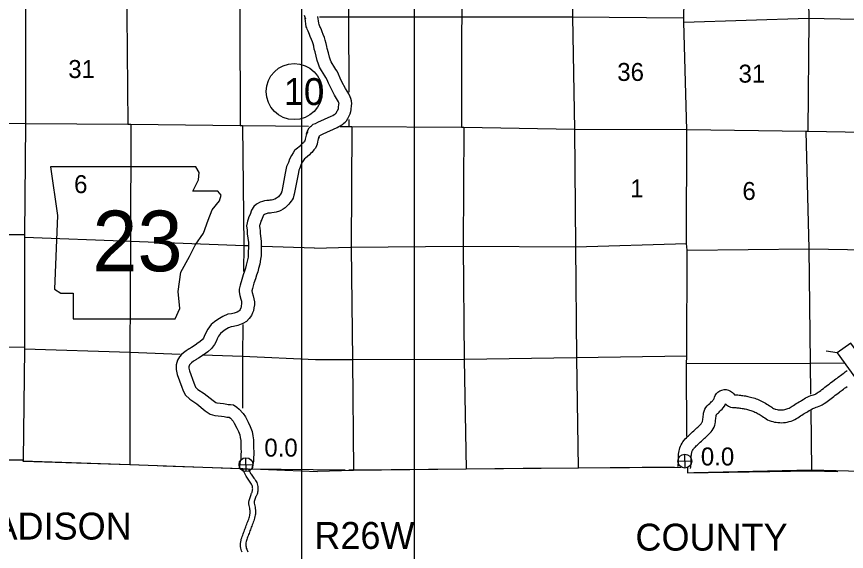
# Model space of a CAD drawing. Extents: x 77230 to 630905, y 790554 to 1662844.
# Drawn here: x 354221 to 393234, y 1564948 to 1590114 of the extents above; entities that cross this region are included whole.
import ezdxf

# ---------------------------------------------------------------- set-up
doc = ezdxf.new("R2010")
doc.units = 0
for name, color, linetype in [('Level 10', 7, 'Continuous'), ('Level 15', 7, 'Continuous'), ('Level 16', 7, 'Continuous'), ('Level 18', 7, 'Continuous'), ('Level 19', 7, 'Continuous'), ('Level 22', 7, 'Continuous'), ('Level 24', 7, 'Continuous'), ('Level 28', 7, 'Continuous'), ('Level 31', 7, 'Continuous'), ('Level 33', 7, 'Continuous'), ('Level 34', 7, 'Continuous'), ('Level 43', 7, 'Continuous')]:
    doc.layers.add(name, color=color, linetype=linetype)

msp = doc.modelspace()

# ---------------------------------------------------------------- linework, layer by layer
at = {"layer": 'Level 10'}
for points in [[(364825, 1564913), (364802, 1564974), (364781, 1565039), (364765, 1565107), (364754, 1565177), (364749, 1565248), (364750, 1565320), (364758, 1565392), (364773, 1565471), (364787, 1565528), (364807, 1565593), (364828, 1565654), (364850, 1565712), (364871, 1565770), (364893, 1565827), (364914, 1565883), (364935, 1565940), (364956, 1565997), (364978, 1566054), (365000, 1566112), (365022, 1566171), (365044, 1566231), (365067, 1566290), (365090, 1566349), (365111, 1566407), (365133, 1566465), (365152, 1566523), (365169, 1566580), (365183, 1566637), (365194, 1566696), (365198, 1566728), (365203, 1566813), (365201, 1566869), (365194, 1566927), (365184, 1566986), (365171, 1567048), (365157, 1567116), (365146, 1567189), (365143, 1567265), (365149, 1567349), (365243, 1567628), (365257, 1567657), (365269, 1567683), (365281, 1567710), (365292, 1567737), (365303, 1567766), (365311, 1567794), (365316, 1567823), (365319, 1567855), (365320, 1567891), (365318, 1567929), (365314, 1567968), (365306, 1568005), (365295, 1568043), (365280, 1568079), (365261, 1568117), (365236, 1568157), (365207, 1568201), (365175, 1568247), (365143, 1568294), (365111, 1568341), (365078, 1568388), (365043, 1568438), (365010, 1568490), (364977, 1568547), (364947, 1568609), (364915, 1568672), (364880, 1568778), (364875, 1568839), (365126, 1568836)], [(365126, 1568836), (365137, 1568789), (365157, 1568743), (365181, 1568699), (365198, 1568664), (365224, 1568621), (365252, 1568575), (365283, 1568530), (365316, 1568483), (365348, 1568436), (365381, 1568389), (365414, 1568342), (365447, 1568292), (365479, 1568240), (365508, 1568183), (365532, 1568125), (365549, 1568065), (365561, 1568006), (365567, 1567949), (365570, 1567895), (365569, 1567840), (365564, 1567787), (365554, 1567736), (365541, 1567690), (365526, 1567649), (365511, 1567611), (365496, 1567578), (365484, 1567552), (365476, 1567535), (365396, 1567299), (365393, 1567262), (365395, 1567213), (365403, 1567159), (365416, 1567100), (365430, 1567034), (365442, 1566963), (365451, 1566889), (365454, 1566810), (365447, 1566705), (365441, 1566658), (365428, 1566585), (365411, 1566514), (365390, 1566447), (365368, 1566382), (365346, 1566321), (365323, 1566261), (365301, 1566201), (365278, 1566142), (365256, 1566083), (365234, 1566024), (365212, 1565967), (365191, 1565909), (365169, 1565852), (365148, 1565796), (365127, 1565739), (365106, 1565682), (365084, 1565626), (365064, 1565570), (365045, 1565514), (365028, 1565460), (365017, 1565417), (365005, 1565355), (365000, 1565305), (364999, 1565255), (365003, 1565205), (365010, 1565156), (365022, 1565107), (365038, 1565057), (365058, 1565005), (365090, 1564929)]]:
    msp.add_lwpolyline(points, dxfattribs=at)
at = {"layer": 'Level 15'}
for points in [[(385737, 1570366), (385723, 1573779), (385728, 1574142), (385742, 1579119), (385724, 1579431), (385733, 1584779), (385590, 1589858), (385587, 1590060), (385688, 1594740)], [(354624, 1594312), (354645, 1590288), (354644, 1585065), (354598, 1579843), (354599, 1579713), (354592, 1574536), (354586, 1574466), (354526, 1569264)], [(367944, 1584949), (364841, 1584980), (364732, 1584975), (359592, 1585040), (359446, 1585039), (354660, 1585067), (351771, 1585111)], [(402337, 1584581), (402130, 1584589), (401996, 1584588), (396829, 1584617), (396669, 1584618), (391418, 1584708), (391330, 1584704), (385741, 1584779), (380454, 1584798), (375249, 1584892), (375133, 1584892), (369975, 1584925), (369847, 1584924), (369429, 1584930)]]:
    msp.add_lwpolyline(points, dxfattribs=at)
at = {"layer": 'Level 16'}
for points in [[(364659, 1594455), (364714, 1590160), (364732, 1584975)], [(375149, 1594584), (375133, 1584892)], [(380314, 1594659), (380350, 1590095), (380458, 1584808), (380504, 1579303), (380538, 1574064), (380630, 1568872)], [(391369, 1594782), (391463, 1590012), (391418, 1584708)], [(359314, 1594367), (359397, 1590218), (359446, 1585039)], [(369798, 1592776), (369827, 1590083), (369840, 1586563)], [(368466, 1590107), (369837, 1590098), (375062, 1590096), (380320, 1590095), (385587, 1590060)], [(385590, 1589858), (391447, 1590032), (396639, 1589923), (401897, 1589918), (404848, 1589866)], [(369845, 1585279), (369847, 1584924)], [(359592, 1585040), (359579, 1579528), (359549, 1574321), (359550, 1569034)], [(364841, 1584980), (364908, 1579342), (364892, 1578126)], [(369975, 1584925), (369944, 1579250), (370018, 1573958), (370064, 1568761)], [(375249, 1584892), (375224, 1579318), (375271, 1573971), (375353, 1568811)], [(391330, 1584704), (391468, 1579209), (391536, 1573830), (391550, 1572343)], [(354598, 1579843), (349364, 1579840), (344063, 1579928), (340508, 1579977)], [(365085, 1579324), (364917, 1579330), (359585, 1579536), (354599, 1579713)], [(368230, 1579211), (365767, 1579300)], [(368230, 1579211), (369924, 1579258), (375223, 1579304), (380495, 1579275), (385724, 1579431)], [(385742, 1579119), (391476, 1579183), (396904, 1579089), (402262, 1578987), (402496, 1578985)], [(364857, 1575618), (364837, 1574123), (364843, 1571686)], [(354592, 1574536), (349283, 1574582), (345273, 1574646)], [(361915, 1574217), (359559, 1574301), (354586, 1574466)], [(368273, 1573968), (364849, 1574113), (362958, 1574180)], [(385728, 1574142), (380534, 1574062), (375279, 1573979), (370020, 1573960), (368273, 1573968)], [(393140, 1573813), (391518, 1573792), (385723, 1573779)], [(391557, 1571630), (391586, 1568764)]]:
    msp.add_lwpolyline(points, dxfattribs=at)
at = {"layer": 'Level 18'}
for points in [[(346093, 1569364), (349212, 1569300), (354526, 1569264), (354523, 1569202), (359550, 1569034), (364699, 1568853)], [(365299, 1568830), (368370, 1568710)], [(385134, 1568915), (380630, 1568872), (378034, 1568843), (375353, 1568811), (370064, 1568761), (368370, 1568710)], [(395649, 1568655), (391586, 1568764), (386057, 1568649)]]:
    msp.add_lwpolyline(points, dxfattribs=at)
at = {"layer": 'Level 19'}
msp.add_line((392797, 1574288), (392275, 1574372), dxfattribs=at)
msp.add_lwpolyline([(392797, 1574288), (394188, 1572361), (394830, 1572825), (393439, 1574751)], close=True, dxfattribs=at)
at = {"layer": 'Level 22'}
for p, q in [((388543, 1572250), (388548, 1572249)), ((388429, 1571661), (388425, 1571662))]:
    msp.add_line(p, q, dxfattribs=at)
for points in [[(367738, 1590180), (367771, 1590088), (367799, 1590001)], [(367856, 1584601), (367906, 1584762), (367981, 1584881), (368041, 1584943), (368086, 1584979), (368167, 1585051), (368276, 1585086), (368382, 1585139), (369017, 1585426), (369083, 1585466), (369159, 1585502), (369174, 1585510), (369181, 1585516), (369210, 1585540), (369235, 1585565), (369244, 1585574), (369257, 1585598), (369299, 1585683), (369320, 1585713), (369325, 1585724), (369335, 1585746), (369349, 1585794), (369354, 1585814), (369360, 1585885), (369372, 1585953), (369377, 1585998), (369380, 1586020), (369378, 1586046), (369369, 1586075), (369361, 1586096), (369314, 1586185), (369168, 1586424), (368972, 1586786), (368886, 1586984), (368817, 1587145), (368761, 1587250), (368717, 1587327), (368641, 1587452), (368554, 1587571), (368463, 1587728), (368408, 1587874), (368356, 1588046), (368308, 1588257), (368251, 1588449), (368216, 1588587), (368195, 1588722), (368164, 1588829), (368132, 1588920), (368081, 1589039), (368029, 1589175), (367993, 1589267), (367956, 1589354), (367924, 1589425), (367888, 1589524), (367867, 1589579), (367839, 1589637), (367791, 1590043)], [(368429, 1584423), (368455, 1584506), (368470, 1584519), (368504, 1584530), (368640, 1584597), (369299, 1584895), (369368, 1584937), (369434, 1584968), (369514, 1585013), (369563, 1585053), (369613, 1585094), (369662, 1585143), (369728, 1585212), (369788, 1585317), (369820, 1585381), (369846, 1585420), (369872, 1585478), (369896, 1585532), (369931, 1585642), (369948, 1585726), (369955, 1585808), (369965, 1585864), (369974, 1585931), (369982, 1586010), (369972, 1586152), (369938, 1586267), (369909, 1586345), (369836, 1586482), (369689, 1586723), (369512, 1587050), (369436, 1587223), (369358, 1587404), (369286, 1587540), (369235, 1587630), (369141, 1587786), (369056, 1587901), (369007, 1587985), (368977, 1588066), (368936, 1588201), (368889, 1588409), (368830, 1588607), (368805, 1588708), (368781, 1588853), (368735, 1589012), (368691, 1589137), (368637, 1589264), (368589, 1589391), (368549, 1589493), (368506, 1589593), (368480, 1589653), (368449, 1589734), (368423, 1589804), (368387, 1590112)], [(367907, 1584710), (367868, 1584634), (367828, 1584528), (367805, 1584411), (367787, 1584340), (367775, 1584270), (367774, 1584269), (367769, 1584259), (367745, 1584231), (367704, 1584181), (367677, 1584150), (367623, 1584104), (367562, 1584040), (367501, 1583983), (367433, 1583925), (367367, 1583880), (367293, 1583810), (367227, 1583705), (367147, 1583584), (367055, 1583411), (366998, 1583253), (366968, 1583184), (366918, 1583066), (366885, 1582904), (366850, 1582741), (366690, 1581885), (366683, 1581860), (366675, 1581829), (366629, 1581760), (366593, 1581709), (366568, 1581678), (366531, 1581638), (366483, 1581596), (366441, 1581567), (366355, 1581522), (366350, 1581520), (366272, 1581498), (366207, 1581482), (366132, 1581470), (366084, 1581464), (366028, 1581457), (365983, 1581454), (365876, 1581441), (365778, 1581410), (365668, 1581376), (365507, 1581285), (365377, 1581174), (365267, 1581005), (365196, 1580807), (365141, 1580695), (365112, 1580586), (365082, 1580493), (365058, 1580410), (365035, 1580269), (365057, 1580069), (365067, 1580010), (365064, 1579898), (365118, 1579485), (365121, 1579254), (365115, 1579038), (365115, 1578897), (365101, 1578793), (365066, 1578600), (365019, 1578418), (364980, 1578276), (364935, 1578131), (364880, 1577958), (364804, 1577745), (364736, 1577478), (364684, 1577293), (364685, 1577167), (364715, 1576992), (364762, 1576822), (364791, 1576716), (364800, 1576641), (364801, 1576603), (364781, 1576501), (364772, 1576434), (364758, 1576403), (364727, 1576327), (364701, 1576288), (364662, 1576251), (364587, 1576206), (364454, 1576152), (364318, 1576126), (364151, 1576105), (363921, 1576008), (363677, 1575868), (363529, 1575745), (363371, 1575622), (363213, 1575400), (363105, 1575207), (363047, 1575059), (363015, 1574988), (362955, 1574912), (362838, 1574812), (362760, 1574755), (362609, 1574659), (362440, 1574545), (362347, 1574486)], [(368442, 1584439), (368417, 1584390), (368407, 1584363), (368391, 1584280), (368374, 1584213), (368356, 1584111), (368325, 1584028), (368271, 1583921), (368203, 1583843), (368162, 1583793), (368101, 1583723), (368036, 1583668), (367985, 1583614), (367900, 1583535), (367797, 1583447), (367757, 1583419), (367732, 1583380), (367663, 1583276), (367605, 1583167), (367556, 1583031), (367519, 1582947), (367494, 1582888), (367473, 1582781), (367438, 1582622), (367276, 1581752), (367263, 1581705), (367228, 1581574), (367176, 1581498), (367124, 1581421), (367073, 1581348), (367022, 1581286), (366948, 1581205), (366850, 1581121), (366752, 1581053), (366643, 1580996), (366584, 1580962), (366426, 1580918), (366327, 1580893), (366215, 1580875), (366159, 1580868), (366082, 1580859), (366035, 1580856), (366003, 1580852), (365957, 1580838), (365907, 1580822), (365853, 1580792), (365832, 1580774), (365808, 1580736), (365749, 1580573), (365706, 1580484), (365688, 1580416), (365655, 1580316), (365644, 1580278), (365640, 1580255), (365652, 1580150), (365668, 1580049), (365665, 1579929), (365717, 1579528), (365722, 1579250), (365715, 1579028), (365714, 1578857), (365694, 1578700), (365652, 1578471), (365598, 1578263), (365556, 1578108), (365507, 1577952), (365449, 1577767), (365379, 1577570), (365315, 1577323), (365286, 1577216), (365302, 1577123), (365341, 1576981), (365382, 1576830), (365399, 1576685), (365403, 1576554), (365373, 1576403), (365356, 1576270), (365310, 1576168), (365259, 1576042), (365163, 1575901), (365030, 1575772), (364855, 1575667), (364625, 1575574), (364412, 1575533), (364307, 1575520), (364187, 1575469), (364020, 1575374), (363905, 1575278), (363809, 1575203), (363721, 1575078), (363648, 1574949), (363600, 1574827), (363533, 1574677), (363391, 1574495), (363210, 1574340), (363097, 1574259), (362938, 1574157), (362768, 1574043), (362669, 1573980)], [(362342, 1574483), (362198, 1574388), (362072, 1574294), (361977, 1574210), (361876, 1574107), (361791, 1573948), (361730, 1573735), (361720, 1573512), (361772, 1573273), (361984, 1572678), (362031, 1572553), (362148, 1572320), (362370, 1572104), (362688, 1571896), (363091, 1571568), (363314, 1571402), (363537, 1571339), (363862, 1571319), (363985, 1571292), (364105, 1571270), (364208, 1571266), (364217, 1571260), (364272, 1571212), (364398, 1571078), (364454, 1570984), (364574, 1570753), (364661, 1570583), (364720, 1570427), (364740, 1570308), (364758, 1570160), (364759, 1570013), (364756, 1569811), (364774, 1569611), (364769, 1569538), (364762, 1569380), (364761, 1569280), (364753, 1569239), (364724, 1569119), (364702, 1568977), (364700, 1568891), (364699, 1568856)], [(362674, 1573983), (362543, 1573896), (362451, 1573828), (362391, 1573775), (362365, 1573748), (362351, 1573722), (362326, 1573637), (362323, 1573563), (362350, 1573438), (362547, 1572885), (362581, 1572795), (362639, 1572680), (362748, 1572574), (363042, 1572381), (363460, 1572042), (363584, 1571950), (363638, 1571934), (363946, 1571915), (364104, 1571880), (364172, 1571868), (364284, 1571863), (364417, 1571844), (364577, 1571741), (364688, 1571646), (364880, 1571441), (364979, 1571276), (365107, 1571028), (365210, 1570827), (365303, 1570583), (365333, 1570393), (365358, 1570200), (365359, 1570011), (365357, 1569832), (365375, 1569619), (365369, 1569507), (365362, 1569364), (365361, 1569216), (365338, 1569108), (365313, 1569003), (365301, 1568924), (365300, 1568878), (365299, 1568837)], [(391311, 1572168), (391382, 1572210), (391481, 1572249), (391554, 1572277), (391626, 1572300), (391687, 1572319), (391737, 1572336), (391779, 1572354), (391796, 1572363), (391859, 1572402), (391907, 1572437), (391964, 1572480), (392025, 1572525), (392086, 1572572), (392150, 1572620), (392216, 1572670), (392283, 1572720), (392351, 1572771), (392419, 1572823), (392487, 1572875), (392553, 1572924), (392582, 1572946), (392676, 1573017), (392743, 1573068), (392792, 1573104), (392847, 1573146), (392903, 1573187), (392960, 1573231), (393019, 1573275), (393075, 1573317), (393128, 1573357), (393179, 1573396), (393228, 1573432), (393272, 1573465)], [(391631, 1571660), (391648, 1571670), (391699, 1571690), (391752, 1571710), (391807, 1571728), (391874, 1571749), (391952, 1571776), (392034, 1571811), (392093, 1571841), (392194, 1571904), (392263, 1571954), (392324, 1572000), (392385, 1572046), (392449, 1572093), (392512, 1572142), (392577, 1572191), (392644, 1572241), (392713, 1572293), (392782, 1572345), (392849, 1572396), (392914, 1572445), (392944, 1572468), (393037, 1572538), (393103, 1572588), (393151, 1572624), (393208, 1572666), (393265, 1572709)], [(385312, 1568950), (385317, 1568980), (385323, 1569012), (385328, 1569042), (385332, 1569074), (385336, 1569105), (385338, 1569136), (385340, 1569173), (385341, 1569214), (385342, 1569255), (385342, 1569313), (385342, 1569352), (385343, 1569404), (385343, 1569463), (385347, 1569528), (385353, 1569599), (385365, 1569674), (385383, 1569749), (385406, 1569823), (385433, 1569896), (385467, 1569969), (385506, 1570041), (385551, 1570111), (385602, 1570179), (385656, 1570242), (385711, 1570298), (385763, 1570348), (385812, 1570393), (385861, 1570438), (385909, 1570483), (385957, 1570527), (386006, 1570573), (386055, 1570619), (386105, 1570665), (386154, 1570710), (386203, 1570755), (386252, 1570800), (386299, 1570844), (386342, 1570884), (386377, 1570918), (386404, 1570948), (386425, 1570977), (386444, 1571007), (386459, 1571037), (386470, 1571066), (386473, 1571079), (386484, 1571138), (386490, 1571187), (386496, 1571242), (386501, 1571304), (386511, 1571379), (386523, 1571456), (386546, 1571544), (386582, 1571636), (386630, 1571721), (386688, 1571797), (386746, 1571859), (386806, 1571914), (386840, 1571945), (386881, 1571984), (386921, 1572022), (386955, 1572054), (386974, 1572075), (386984, 1572090), (386995, 1572111), (387010, 1572150), (387034, 1572211), (387070, 1572289), (387125, 1572371), (387196, 1572444), (387283, 1572503), (387378, 1572543), (387481, 1572563), (387585, 1572562), (387691, 1572540), (387791, 1572495), (387878, 1572432), (387939, 1572366), (387974, 1572320), (387977, 1572317), (387979, 1572316), (388023, 1572315), (388076, 1572312), (388134, 1572308), (388192, 1572303), (388250, 1572296), (388307, 1572289), (388367, 1572281), (388426, 1572271), (388485, 1572261), (388543, 1572250)], [(388548, 1572249), (388606, 1572237), (388666, 1572223), (388729, 1572208), (388794, 1572191), (388859, 1572172), (388923, 1572152), (388988, 1572129), (389054, 1572105), (389120, 1572078), (389185, 1572049), (389249, 1572019), (389312, 1571987), (389374, 1571953), (389436, 1571918), (389498, 1571881), (389559, 1571842), (389619, 1571802), (389674, 1571764), (389723, 1571731), (389767, 1571703), (389807, 1571680), (389846, 1571661), (389884, 1571647), (389923, 1571635), (389971, 1571625), (390023, 1571616), (390074, 1571610), (390124, 1571606), (390176, 1571606), (390229, 1571608), (390282, 1571614), (390335, 1571623), (390388, 1571635), (390439, 1571650), (390488, 1571669), (390537, 1571691), (390585, 1571717), (390634, 1571746), (390687, 1571781), (390745, 1571820), (390806, 1571861), (390873, 1571905), (390941, 1571947), (391008, 1571987), (391068, 1572021), (391119, 1572053), (391196, 1572094), (391245, 1572123), (391311, 1572168)], [(385904, 1568850), (385909, 1568879), (385915, 1568914), (385921, 1568954), (385927, 1568998), (385933, 1569047), (385937, 1569100), (385939, 1569150), (385941, 1569200), (385942, 1569251), (385942, 1569309), (385942, 1569349), (385943, 1569399), (385943, 1569443), (385945, 1569485), (385949, 1569523), (385954, 1569558), (385963, 1569593), (385973, 1569628), (385987, 1569665), (386004, 1569701), (386023, 1569736), (386044, 1569769), (386069, 1569802), (386097, 1569835), (386133, 1569871), (386174, 1569910), (386220, 1569953), (386268, 1569997), (386317, 1570042), (386366, 1570088), (386415, 1570134), (386464, 1570179), (386512, 1570224), (386561, 1570269), (386609, 1570314), (386657, 1570358), (386707, 1570403), (386758, 1570451), (386812, 1570505), (386869, 1570569), (386923, 1570640), (386969, 1570716), (387010, 1570797), (387042, 1570882), (387059, 1570947), (387077, 1571047), (387086, 1571118), (387093, 1571186), (387098, 1571240), (387105, 1571291), (387111, 1571334), (387118, 1571360), (387125, 1571376), (387133, 1571391), (387146, 1571408), (387168, 1571432), (387213, 1571474), (387247, 1571505), (387291, 1571546), (387336, 1571588), (387386, 1571637), (387445, 1571702), (387501, 1571783), (387543, 1571865), (387552, 1571889), (387603, 1571839), (387686, 1571783), (387779, 1571743), (387871, 1571723), (387943, 1571717), (387995, 1571715), (388041, 1571713), (388086, 1571710), (388132, 1571706), (388180, 1571700), (388229, 1571694), (388278, 1571688), (388327, 1571680), (388377, 1571671), (388429, 1571661)], [(388425, 1571662), (388479, 1571650), (388531, 1571639), (388583, 1571626), (388633, 1571613), (388684, 1571598), (388735, 1571582), (388787, 1571564), (388836, 1571546), (388885, 1571526), (388934, 1571504), (388984, 1571480), (389034, 1571455), (389084, 1571428), (389133, 1571400), (389182, 1571371), (389231, 1571339), (389281, 1571306), (389334, 1571269), (389394, 1571229), (389459, 1571187), (389531, 1571147), (389610, 1571109), (389693, 1571078), (389777, 1571053), (389856, 1571036), (389933, 1571023), (390015, 1571012), (390100, 1571006), (390186, 1571005), (390274, 1571010), (390363, 1571019), (390453, 1571034), (390543, 1571055), (390632, 1571082), (390719, 1571114), (390803, 1571153), (390881, 1571195), (390954, 1571238), (391019, 1571281), (391080, 1571322), (391139, 1571362), (391195, 1571399), (391252, 1571434), (391310, 1571468), (391374, 1571505), (391420, 1571534), (391491, 1571572), (391565, 1571615), (391631, 1571660)]]:
    msp.add_lwpolyline(points, dxfattribs=at)
at = {"layer": 'Level 24'}
msp.add_lwpolyline([(355808, 1583043), (356150, 1580759), (355998, 1577295), (356303, 1577105), (356874, 1577105), (356874, 1575887), (361670, 1575887), (361898, 1576382), (361822, 1577181), (361936, 1578095), (362355, 1578818), (362622, 1579351), (363002, 1579922), (363231, 1580531), (363421, 1581026), (363764, 1581444), (363840, 1581711), (363687, 1581901), (362507, 1581901), (362774, 1582434), (362812, 1582777), (362654, 1583040)], close=True, dxfattribs=at)
at = {"layer": 'Level 28'}
for p, q in [((372910, 1655440), (372910, 1475921)), ((367630, 1481201), (367630, 1651480))]:
    msp.add_line(p, q, dxfattribs=at)
at = {"layer": 'Level 33'}
msp.add_circle((367274, 1586585), 1320, dxfattribs=at)
at = {"layer": 'Level 34'}
for p, q in [((385648, 1568873), (385633, 1569523)), ((365014, 1568704), (364999, 1569355)), ((385315, 1569191), (385966, 1569206)), ((364681, 1569022), (365332, 1569037))]:
    msp.add_line(p, q, dxfattribs=at)
for centre in [(385640, 1569198), (365006, 1569029)]:
    msp.add_circle(centre, 326, dxfattribs=at)
at = {"layer": 'Level 43'}
for p, q in [((354509, 1569249), (354510, 1569202)), ((385758, 1568901), (385761, 1568640))]:
    msp.add_line(p, q, dxfattribs=at)
for points in [[(349207, 1569293), (354509, 1569249)], [(360847, 1568971), (359538, 1569017), (354510, 1569202)], [(364860, 1568829), (364833, 1568829), (364826, 1568829), (361107, 1568962)], [(369674, 1568776), (365151, 1568825)], [(385454, 1568899), (380644, 1568864), (375365, 1568811), (370068, 1568772), (369848, 1568774)], [(385758, 1568901), (385726, 1568901)], [(385761, 1568640), (391579, 1568743), (392828, 1568712)]]:
    msp.add_lwpolyline(points, dxfattribs=at)

# ---------------------------------------------------------------- texts
at = {"layer": 'Level 16'}
for s, height, p in [('31', 844.8, (356650, 1587224)), ('36', 844.8, (382460, 1587086)), ('31', 844.8, (388163, 1587006)), ('6', 845, (356924, 1581807)), ('1', 845, (383072, 1581606)), ('6', 845, (388344, 1581486))]:
    msp.add_text(s, height=height, dxfattribs=at).set_placement(p)
at = {"layer": 'Level 24'}
msp.add_text('23', height=2851.2, dxfattribs=at).set_placement((357784, 1578131))
at = {"layer": 'Level 28'}
for s, p in [('MADISON', (351724, 1565506)), ('R26W', (368219, 1565065)), ('COUNTY', (383317, 1564985))]:
    msp.add_text(s, height=1267.2, dxfattribs=at).set_placement(p)
at = {"layer": 'Level 31'}
for p in [(365868, 1569409), (386390, 1568992)]:
    msp.add_text('0.0', height=844.8, dxfattribs=at).set_placement(p)
at = {"layer": 'Level 33'}
msp.add_text('10', height=1267.2, dxfattribs=at).set_placement((366785, 1585952))

doc.saveas('drawing.dxf')
